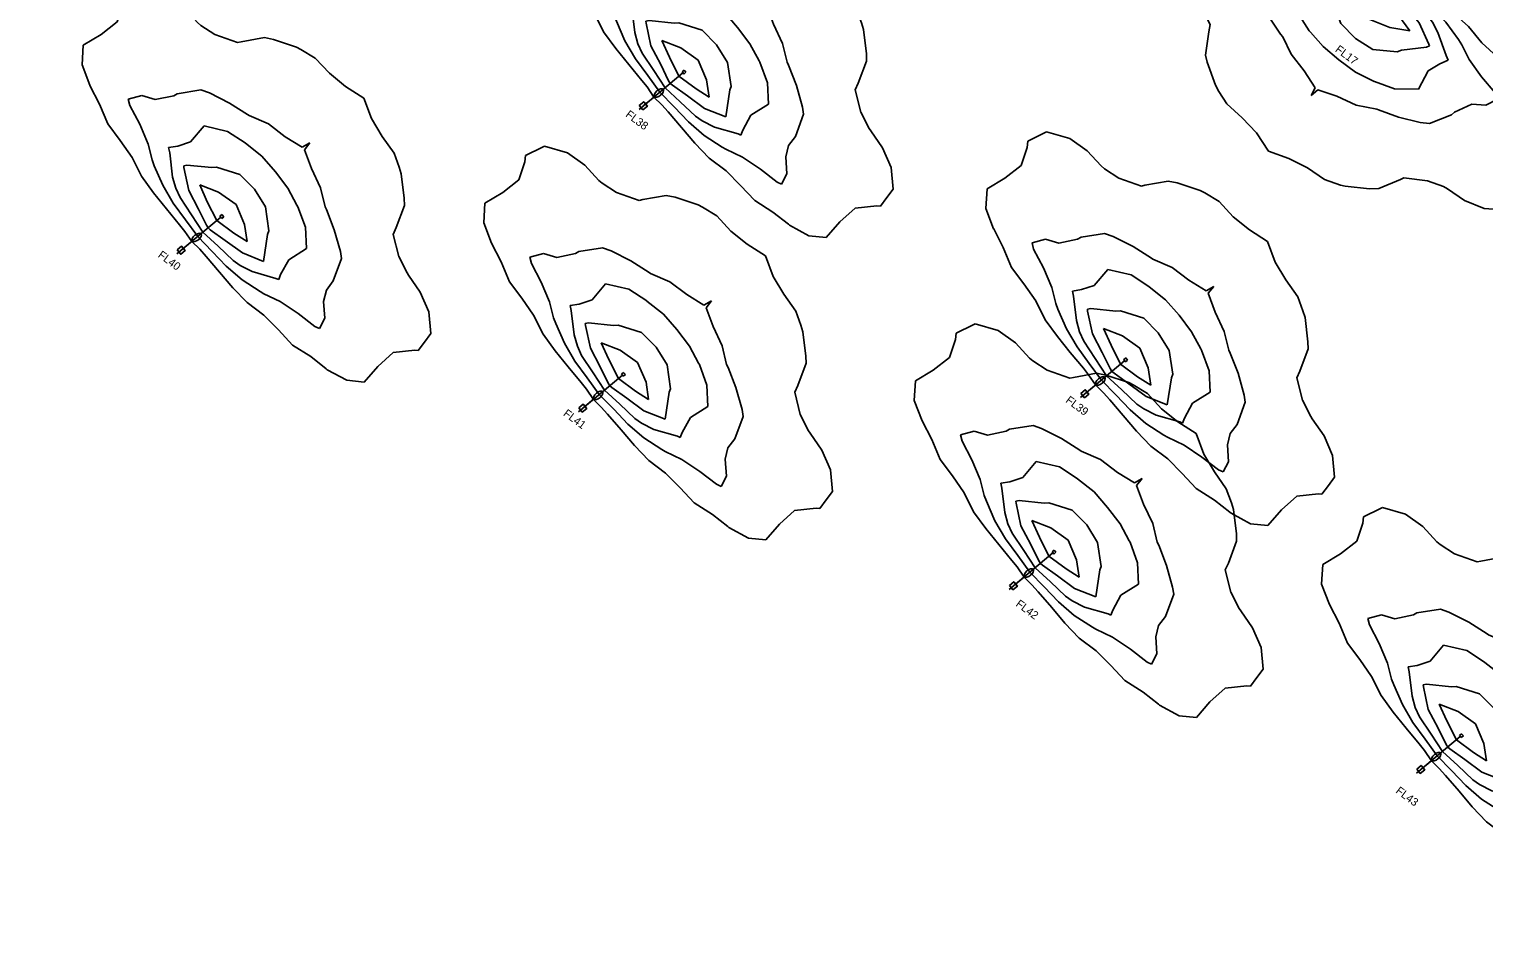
# Model space of a CAD drawing. Extents: x 1322666 to 1327584, y 458075 to 462260.
# Drawn here: x 1325078 to 1325587, y 459544 to 459866 of the extents above; entities that cross this region are included whole.
import ezdxf

# ---------------------------------------------------------------- set-up
doc = ezdxf.new("R2010")
doc.units = 0
for name, color, linetype in [('Default', 7, 'Continuous'), ('DR_P_Culvert', 7, 'Continuous'), ('UT_X_Misc_Cells', 7, 'Continuous')]:
    doc.layers.add(name, color=color, linetype=linetype)

# ---------------------------------------------------------------- blocks, each defined once
blk = doc.blocks.new('AGI32-IDj66arb-Project_1-LUMINAIRE-ERL2_19C330______Symbol')
at = {"layer": 'Default'}
for p, q in [((-0.03, 0), (0.03, 0)), ((0, 0.13), (0.24, 0.13)), ((0, -0.13), (0, 0.13)), ((0, 0.13), (0, 0.13)), ((0, 0.13), (0.24, 0.13)), ((0.24, 0.13), (0, 0.13)), ((0, -0.13), (0, 0.13)), ((0, 0.13), (0, 0.13)), ((0, 0.13), (0, -0.13)), ((0.24, 0.13), (0, 0.13)), ((0, 0.13), (0, -0.13)), ((0, -0.03), (0, 0.03)), ((0, 0.03), (0.03, 0)), ((0, -0.03), (0.03, 0)), ((0.24, 0.13), (0.24, -0.13)), ((0.24, 0.13), (0.24, 0.13)), ((0.24, 0.13), (0.24, 0.13)), ((0.24, 0.13), (0.24, -0.13)), ((0.24, -0.13), (0.24, 0.13)), ((0.24, -0.13), (0.24, 0.13)), ((0.24, -0.13), (0, -0.13)), ((0.24, -0.13), (0, -0.13)), ((0, -0.13), (0, -0.13)), ((0, -0.13), (0.24, -0.13)), ((0, -0.13), (0, -0.13)), ((0, -0.13), (0.24, -0.13)), ((0.24, -0.13), (0.24, -0.13)), ((0.24, -0.13), (0.24, -0.13))]:
    blk.add_line(p, q, dxfattribs=at)
blk = doc.blocks.new('AGI32-IDj66arb-Project_1-LUMINAIRE-ERL2_19C330______64-1')
at = {"layer": 'Default'}
blk.add_blockref('AGI32-IDj66arb-Project_1-LUMINAIRE-ERL2_19C330______Symbol', (0, 0), dxfattribs=at)
blk = doc.blocks.new('AGI32-IDj66arb-Project_1-LUMINAIRE-ERL2_19C330______Template1')
at = {"layer": 'Default'}
for p, q in [((4.29, 18.29), (5.49, 19.56)), ((5.49, 19.56), (7.31, 19.28)), ((9.14, 19.22), (10.58, 20.11)), ((10.58, 20.11), (10.97, 20.5)), ((10.97, 20.5), (12.6, 20.11)), ((12.6, 20.11), (12.8, 20.07)), ((12.8, 20.07), (13.99, 18.29)), ((3.66, 16.46), (4.29, 18.29)), ((7.31, 19.28), (9.14, 19.22)), ((13.99, 18.29), (14.48, 16.46)), ((3.25, 14.63), (3.66, 16.45)), ((3.66, 16.45), (3.66, 16.46)), ((14.48, 16.46), (14.57, 14.63)), ((2.69, 12.8), (3.25, 14.63)), ((14.57, 14.63), (14.63, 14.24)), ((14.63, 14.24), (15.08, 12.8)), ((5.23, 12.8), (5.49, 13.32)), ((5.49, 13.32), (6.62, 12.8)), ((2.59, 10.97), (2.69, 12.8)), ((4.85, 10.97), (5.23, 12.8)), ((6.62, 12.8), (7.31, 11.77)), ((7.31, 11.77), (8.8, 10.97)), ((15.08, 12.8), (16.17, 10.97)), ((2.44, 9.14), (2.59, 10.97)), ((4.29, 9.14), (4.85, 10.97)), ((8.8, 10.97), (9.14, 10.91)), ((9.14, 10.91), (10.97, 9.83)), ((16.17, 10.97), (16.46, 10.82)), ((16.46, 10.82), (18.29, 9.79)), ((2, 7.31), (2.44, 9.14)), ((3.66, 7.83), (4.29, 9.14)), ((10.97, 9.83), (11.39, 9.14)), ((11.39, 9.14), (12.17, 7.31)), ((18.29, 9.79), (18.8, 9.14)), ((18.8, 9.14), (19.94, 7.31)), ((3.47, 7.31), (3.66, 7.83)), ((1.89, 5.49), (2, 7.31)), ((2.95, 5.49), (3.47, 7.31)), ((4.09, 5.49), (5.27, 7.31)), ((5.27, 7.31), (5.49, 7.72)), ((5.49, 7.72), (6.19, 7.31)), ((6.19, 7.31), (7.31, 6.87)), ((7.31, 6.87), (9.14, 7.19)), ((9.14, 7.19), (10.42, 5.49)), ((12.17, 7.31), (12.76, 5.49)), ((19.94, 7.31), (20.11, 6.9)), ((20.11, 6.9), (20.59, 5.49)), ((1.86, 3.66), (1.89, 5.49)), ((2.64, 3.66), (2.95, 5.49)), ((3.66, 4.54), (4.09, 5.49)), ((4.43, 3.66), (5.39, 5.49)), ((5.39, 5.49), (5.49, 5.63)), ((5.49, 5.63), (5.75, 5.49)), ((5.75, 5.49), (7.31, 3.9)), ((10.42, 5.49), (10.97, 3.69)), ((12.76, 5.49), (12.8, 5.34)), ((12.8, 5.34), (13.64, 3.66)), ((20.59, 5.49), (20.69, 3.66)), ((3.42, 3.66), (3.66, 4.54)), ((7.31, 3.9), (7.65, 3.66)), ((1.85, 1.83), (1.86, 3.66)), ((2.53, 1.83), (2.64, 3.66)), ((3.22, 1.83), (3.42, 3.66)), ((4.03, 1.83), (4.43, 3.66)), ((5.05, 1.83), (5.49, 3.41)), ((5.49, 3.41), (6.36, 1.83)), ((7.65, 3.66), (8.83, 1.83)), ((10.97, 3.69), (10.98, 3.66)), ((10.98, 3.66), (11.36, 1.83)), ((13.64, 3.66), (14.06, 1.83)), ((20.69, 3.66), (21.05, 1.83)), ((1.83, 1.08), (1.85, 1.83)), ((2.41, 0), (2.53, 1.83)), ((3.01, 0), (3.22, 1.83)), ((3.66, 0.28), (4.03, 1.83)), ((4.62, 0), (5.05, 1.83)), ((6.36, 1.83), (6.85, 0)), ((8.83, 1.83), (8.98, 0)), ((11.36, 1.83), (11.4, 0)), ((14.06, 1.83), (14.63, 0.14)), ((21.05, 1.83), (21.63, 0)), ((1.73, 0), (1.83, 1.08)), ((3.62, 0), (3.66, 0.28)), ((14.63, 0.14), (15.4, 0)), ((1.83, -0.98), (1.73, 0)), ((1.85, -1.83), (1.83, -0.98)), ((2.55, -1.83), (2.41, 0)), ((3.25, -1.83), (3.01, 0)), ((3.66, -0.25), (3.62, 0)), ((4.07, -1.83), (3.66, -0.25)), ((5.07, -1.83), (4.62, 0)), ((6.85, 0), (6.29, -1.83)), ((8.98, 0), (8.72, -1.83)), ((11.4, 0), (11.31, -1.83)), ((14.63, -0.15), (14.04, -1.83)), ((15.4, 0), (14.63, -0.15)), ((21.63, 0), (20.99, -1.83)), ((1.88, -3.66), (1.85, -1.83)), ((2.67, -3.66), (2.55, -1.83)), ((3.47, -3.66), (3.25, -1.83)), ((4.53, -3.66), (4.07, -1.83)), ((5.49, -3.15), (5.07, -1.83)), ((6.29, -1.83), (5.49, -3.15)), ((8.72, -1.83), (7.6, -3.66)), ((11.31, -1.83), (10.97, -3.51)), ((14.04, -1.83), (13.56, -3.66)), ((20.99, -1.83), (20.7, -3.66)), ((1.89, -5.49), (1.88, -3.66)), ((2.97, -5.49), (2.67, -3.66)), ((3.66, -4.38), (3.47, -3.66)), ((5.49, -5.44), (4.53, -3.66)), ((7.31, -3.83), (5.49, -5.44)), ((7.6, -3.66), (7.31, -3.83)), ((10.94, -3.66), (10.29, -5.49)), ((10.97, -3.51), (10.94, -3.66)), ((13.56, -3.66), (12.8, -5.21)), ((20.7, -3.66), (20.55, -5.49)), ((4.15, -5.49), (3.66, -4.38)), ((2.03, -7.31), (1.89, -5.49)), ((3.54, -7.31), (2.97, -5.49)), ((5.37, -7.31), (4.15, -5.49)), ((10.29, -5.49), (9.14, -7.01)), ((12.73, -5.49), (12.12, -7.31)), ((12.8, -5.21), (12.73, -5.49)), ((20.55, -5.49), (20.11, -6.73)), ((2.46, -9.14), (2.03, -7.31)), ((3.66, -7.66), (3.54, -7.31)), ((4.35, -9.14), (3.66, -7.66)), ((5.49, -7.55), (5.37, -7.31)), ((5.91, -7.31), (5.49, -7.55)), ((7.31, -6.76), (5.91, -7.31)), ((9.14, -7.01), (7.31, -6.76)), ((12.12, -7.31), (11.3, -9.14)), ((19.86, -7.31), (18.68, -9.14)), ((20.11, -6.73), (19.86, -7.31)), ((2.61, -10.97), (2.46, -9.14)), ((4.89, -10.97), (4.35, -9.14)), ((10.97, -9.68), (9.14, -10.74)), ((11.3, -9.14), (10.97, -9.68)), ((18.29, -9.64), (16.46, -10.68)), ((18.68, -9.14), (18.29, -9.64)), ((2.71, -12.8), (2.61, -10.97)), ((5.29, -12.8), (4.89, -10.97)), ((7.31, -11.59), (6.44, -12.8)), ((8.15, -10.97), (7.31, -11.59)), ((9.14, -10.74), (8.15, -10.97)), ((15.87, -10.97), (14.99, -12.8)), ((16.46, -10.68), (15.87, -10.97)), ((3.3, -14.63), (2.71, -12.8)), ((5.49, -13.2), (5.29, -12.8)), ((6.44, -12.8), (5.49, -13.2)), ((14.99, -12.8), (14.63, -14.39)), ((3.66, -16.33), (3.3, -14.63)), ((14.6, -14.63), (14.44, -16.46)), ((14.63, -14.39), (14.6, -14.63)), ((3.68, -16.46), (3.66, -16.33)), ((4.41, -18.29), (3.68, -16.46)), ((14.44, -16.46), (13.9, -18.29)), ((5.49, -19.4), (4.41, -18.29)), ((7.31, -19.11), (5.49, -19.4)), ((9.14, -19.03), (7.31, -19.11)), ((10.75, -20.11), (9.14, -19.03)), ((13.9, -18.29), (12.8, -19.89)), ((10.97, -20.33), (10.75, -20.11)), ((11.9, -20.11), (10.97, -20.33)), ((12.8, -19.89), (11.9, -20.11))]:
    blk.add_line(p, q, dxfattribs=at)
blk = doc.blocks.new('AGI32-IDj66arb-Project_1-LUMINAIRE-ERL2_19C330______64')
at = {"layer": 'Default'}
for q in [(5.08, 0), (0, 0)]:
    blk.add_line((0, 0), q, dxfattribs=at)
for name, p in [('AGI32-IDj66arb-Project_1-LUMINAIRE-ERL2_19C330______Template1', (0, 0)), ('AGI32-IDj66arb-Project_1-LUMINAIRE-ERL2_19C330______64-1', (5.08, 0))]:
    blk.add_blockref(name, p, dxfattribs=at)

msp = doc.modelspace()

# ---------------------------------------------------------------- linework, layer by layer
at = {"layer": 'DR_P_Culvert'}
for p, q in [((1325292.78, 459838.83), (1325296.65, 459842)), ((1325131.12, 459788.3), (1325134.98, 459791.47)), ((1325447.24, 459738.09), (1325451.1, 459741.26)), ((1325271.59, 459733.08), (1325275.45, 459736.25)), ((1325422.22, 459670.91), (1325426.08, 459674.08)), ((1325564.69, 459606.66), (1325568.56, 459609.84))]:
    msp.add_line(p, q, dxfattribs=at)
for points in [[(1325291.38, 459838.97), (1325292.92, 459840.24), (1325294.19, 459838.69), (1325292.65, 459837.42)], [(1325129.71, 459788.44), (1325131.26, 459789.71), (1325132.53, 459788.16), (1325130.98, 459786.89)], [(1325445.83, 459738.23), (1325447.38, 459739.5), (1325448.65, 459737.95), (1325447.1, 459736.68)], [(1325270.18, 459733.21), (1325271.73, 459734.48), (1325273, 459732.94), (1325271.45, 459731.67)], [(1325420.81, 459671.05), (1325422.35, 459672.32), (1325423.62, 459670.77), (1325422.08, 459669.5)], [(1325563.29, 459606.8), (1325564.83, 459608.07), (1325566.1, 459606.52), (1325564.55, 459605.25)]]:
    msp.add_lwpolyline(points, close=True, dxfattribs=at)
for centre in [(1325298.19, 459843.27), (1325136.53, 459792.74), (1325452.65, 459742.53), (1325277, 459737.52), (1325427.62, 459675.35), (1325570.1, 459611.11)]:
    msp.add_ellipse(centre, major_axis=(1.55, 1.27), ratio=0.5, dxfattribs=at)

# ---------------------------------------------------------------- block references
at = {"layer": 'DR_P_Culvert', "yscale": 3.9370000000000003}
for p, xscale, rotation in [((1325291.28, 459837.53), 3.937, 39.81756765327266), ((1325563.41, 459890.41), 3.9370000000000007, -127.5957929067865), ((1325129.62, 459787), 3.937, 39.81756765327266), ((1325445.74, 459736.79), 3.937, 39.81756765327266), ((1325270.09, 459731.77), 3.937, 39.81756765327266), ((1325420.71, 459669.61), 3.937, 39.81756765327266), ((1325563.19, 459605.36), 3.937, 39.81756765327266)]:
    msp.add_blockref('AGI32-IDj66arb-Project_1-LUMINAIRE-ERL2_19C330______64', p, dxfattribs=dict(at, xscale=xscale, rotation=rotation))

# ---------------------------------------------------------------- texts
at = {"layer": 'UT_X_Misc_Cells'}
for s, p in [('FL17', (1325534.57, 459858.02)), ('FL38', (1325286.33, 459835.25)), ('FL40', (1325122.78, 459786.11)), ('FL41', (1325264.56, 459730.66)), ('FL39', (1325440.28, 459735.31)), ('FL42', (1325422.82, 459664.05)), ('FL43', (1325555.72, 459598.66))]:
    msp.add_text(s, height=2.8, rotation=323.4759, dxfattribs=at).set_placement(p)

doc.saveas('drawing.dxf')
